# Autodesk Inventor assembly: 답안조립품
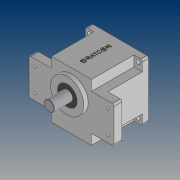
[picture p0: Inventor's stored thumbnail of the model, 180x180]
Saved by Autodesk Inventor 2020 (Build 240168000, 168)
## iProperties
Created: 2020-07
Part Number: 답안조립품
Document SubType Name: Assembly
Designer: PC312-
Author: PC312-
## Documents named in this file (10)
- C:\Users\PC312-\Desktop\700718V1013\답안조립품.iam
- C:\Users\PC312-\Desktop\700718V1013\본체.ipt
- C:\Users\PC312-\Desktop\700718V1013\오일 실 17 32 8.ipt
- C:\Users\PC312-\Desktop\700718V1013\커버.ipt
- C:\Users\PC312-\Desktop\700718V1013\오일 실 8 22 7.ipt
- C:\Users\PC312-\Desktop\700718V1013\서브 축.ipt
- C:\Users\PC312-\Desktop\700718V1013\베어링 608.ipt
- C:\Users\PC312-\Desktop\700718V1013\베어링 6003.ipt
- C:\Users\PC312-\Desktop\700718V1013\메인 축.ipt
- C:\Users\PC312-\Desktop\700718V1013\볼트 M4.ipt
